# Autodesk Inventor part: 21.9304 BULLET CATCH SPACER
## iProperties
Created: 2012-06
Part Number: 21.9304 BULLET CATCH SPACER
Material: ABS Plastic
Document SubType Name: Modeling
Designer: Administrator
Mass: 4.5057 g
Surface Area: 32.1829 cm^2
Volume: 4.25066 cm^3
Density: 1.06 g/cm^3
Author: Administrator
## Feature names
1. Extrusion1
2. Extrusion2
